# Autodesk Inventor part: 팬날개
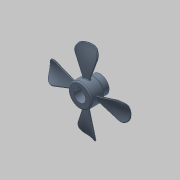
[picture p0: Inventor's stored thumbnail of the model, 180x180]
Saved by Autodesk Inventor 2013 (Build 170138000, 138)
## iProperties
Company: 한국ATC센터
Created: 2016-06
Part Number: 팬날개
Document SubType Name: Modeling
Designer: mdu
Density: 1.493 g/cm^3
Material: PC/ABS 플라스틱
Mass: 34.8717 g
Surface Area: 136.354 cm^2
Volume: 23.3568 cm^3
Author: mdu
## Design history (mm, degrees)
sketch "스케치1"
  geometry: L1 (-15, 0)-(15, 0); L2 (-15, 0)-(-15, 17); L3 (-15, 17)-(5, 17); L4 (5, 17)-(5, 13); L5 (5, 13)-(15, 13); L6 (15, 13)-(15, 0); 2 further points
  constraints: 12 end point, 3 parallel, 2 perpendicular, 1 coincident, 1 horizontal, 1 midpoint
  dimensions: "d0" = 30 distance of L1.start L1.end; "d8" = 34 diameter of L3 L1; "d10" = 26 diameter of L5 L1; "d32" = 20 distance of L2.end L3.end
revolve "회전1" sketch "스케치1" stored, may be unused: angle "d11" = 90 deg
node "작업 평면2"
sketch "스케치7"
  geometry: L1 (-15, 17)-(5, 17) reference; L2 (-15, -17)-(5, -17) reference; L3 (-5, 17)-(-5, -17); A1 r 35 centre (-38.719, -8.43) between (-4, -4) and (-6, 4); 1 further point
  constraints: 2 end point, 2 midpoint, 2 point on circle, 1 centre point
  dimensions: "d36" = 35 radius of A1; "d37" = 13 distance from line of A1.start L2; "d38" = 13 distance from line of A1.end L1; "d45" = 1 distance from line of A1.end L3; "d46" = 1 distance from line of A1.start L3
sketch "3D 스케치1"
  geometry: L1 through (0, 0) direction (1, 0) reference; L2 through (0, 0) direction (1, 0) reference; 13 other entities
  constraints: 2 collinear
  node "투영 원본 위치 스케치7"
sketch "스케치8"
  geometry: L1 (-15, 17)-(5, 17) reference; L2 (-15, -17)-(5, -17) reference; L3 (-5, 17)-(-5, -17); A1 r 30 centre (-28.74, -3.591) between (-3, -19) and (-9, 19); 1 further point
  constraints: 2 end point, 2 midpoint, 2 point on circle, 1 centre point
  dimensions: "d43" = 30 radius of A1; "d47" = 4 distance from line of A1.end L3; "d48" = 2 distance from line of A1.start L3; "d58" = 2 distance from line of A1.end L1; "d59" = 2 distance from line of A1.start L2
sketch "3D 스케치2"
sketch "3D 스케치3"
feature "경계 패치1" sketch "3D 스케치2", "3D 스케치3" dims "d50" = 0
feature "연장1" dims "d55" = 2
feature "두껍게 하기1" dims "d51" = 2, "d52" = 2
sketch "스케치9"
  geometry: C1 r 59 at (0, 0); 1 further point
  constraints: 1 centre point, 1 coincident
  dimensions: "d60" = 118 diameter of C1
extrude "돌출2" sketch "스케치9" distance "d62" = 200; taper "d63" = 0 deg
fillet "모깎기6" dims "d64" = 10
fillet "모깎기7" dims "d66" = 0.8
fillet "모깎기8" dims "d67" = 0.8
sketch "스케치2"
  geometry: L1 (-2.5, 8.124)-(-2.5, 10.8); L2 (-2.5, 10.8)-(2.5, 10.8); L3 (2.5, 10.8)-(2.5, 8.124); A1 r 8.5 centre (0, 0) between (-2.5, 8.124) and (2.5, 8.124); 1 further point
  constraints: 6 end point, 2 parallel, 2 point on circle, 1 centre point, 1 coincident, 1 horizontal, 1 vertical
  dimensions: "d12" = 17 diameter of A1; "d13" = 5 distance of L1.end L2.end; "d14" = 19.3 dimension on A1 L2 (computed from d12)
extrude "돌출1" cut sketch "스케치2" stored distance "d15" = 10; taper "d16" = 0 deg
chamfer "모따기1" distance "d17" = 1; stored, may be unused: second distance "d18" = 2, angle "d19" = 45 deg
node "작업 평면1"
sketch "스케치3"
  geometry: L1 (5, -13)-(5, 13) reference; 3 further points
  constraints: 1 horizontal alignment, 1 midpoint
  dimensions: "d20" = 5 distance from line of L1 point (0, 0)
hole "구멍1" sketch "스케치3" at (0, 0) diameter "d21" = 3.242; stored, may be unused: countersink angle "d25" = 90 deg, drill point angle "d27" = 118 deg; dims "d22" = 6, "d23" = 4, "d24" = 2, "d26" = 8
fillet "모깎기9" dims "d77" = 2
fillet "모깎기10" dims "d78" = 2
fillet "모깎기11" dims "d79" = 2
node "솔리드1"
pattern_circular "원형 패턴1" dims "d69" = 360 deg
pattern_circular "원형 패턴2" dims angle "d72" = 360 deg
pattern_circular "원형 패턴3" dims angle "d75" = 360 deg
node "투영 원본 위치 스케치8"
node "곡면1"
node "곡면2"
node "곡면3"
node "곡면4"
feature "경계 패치2"
feature "경계 패치3"
feature "경계 패치4"
